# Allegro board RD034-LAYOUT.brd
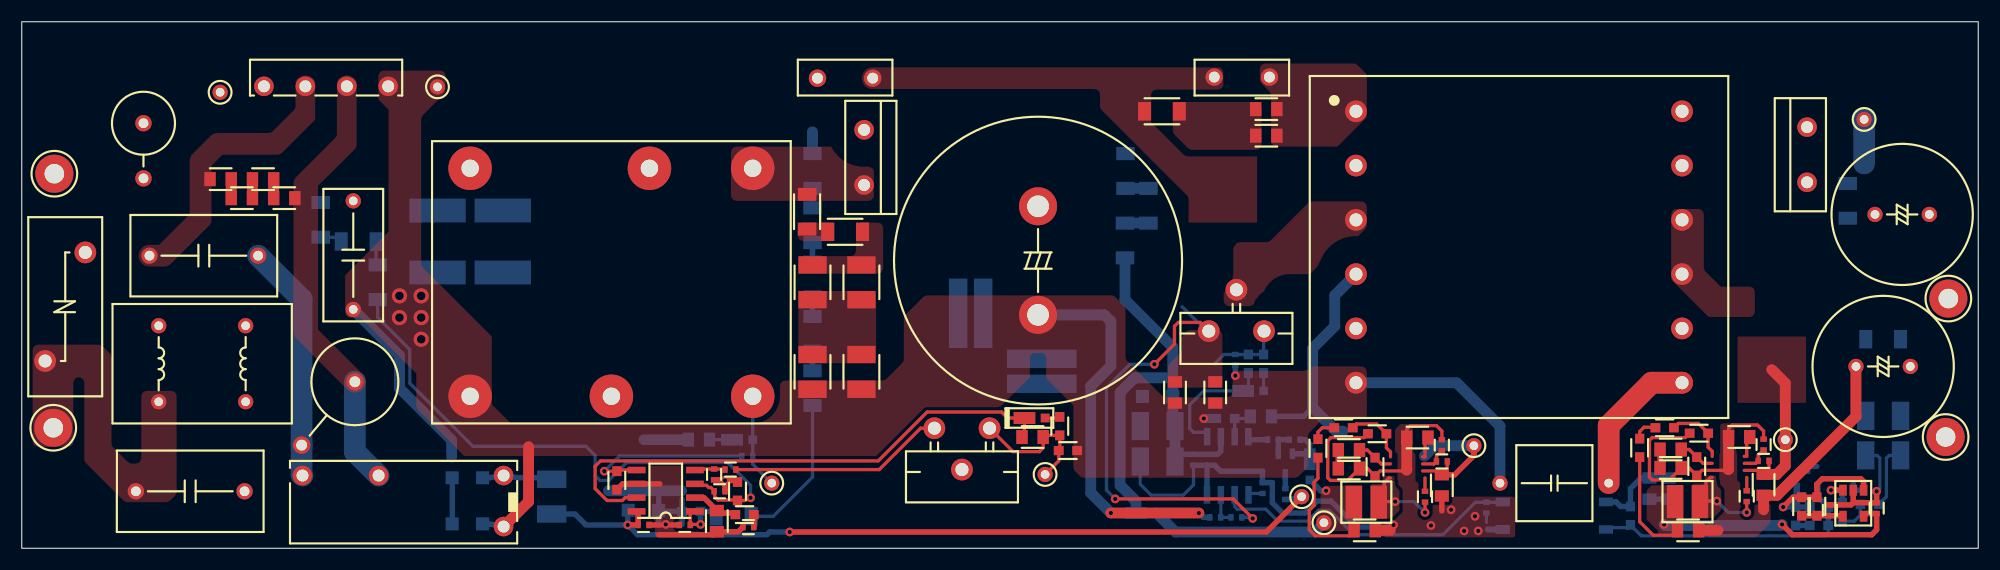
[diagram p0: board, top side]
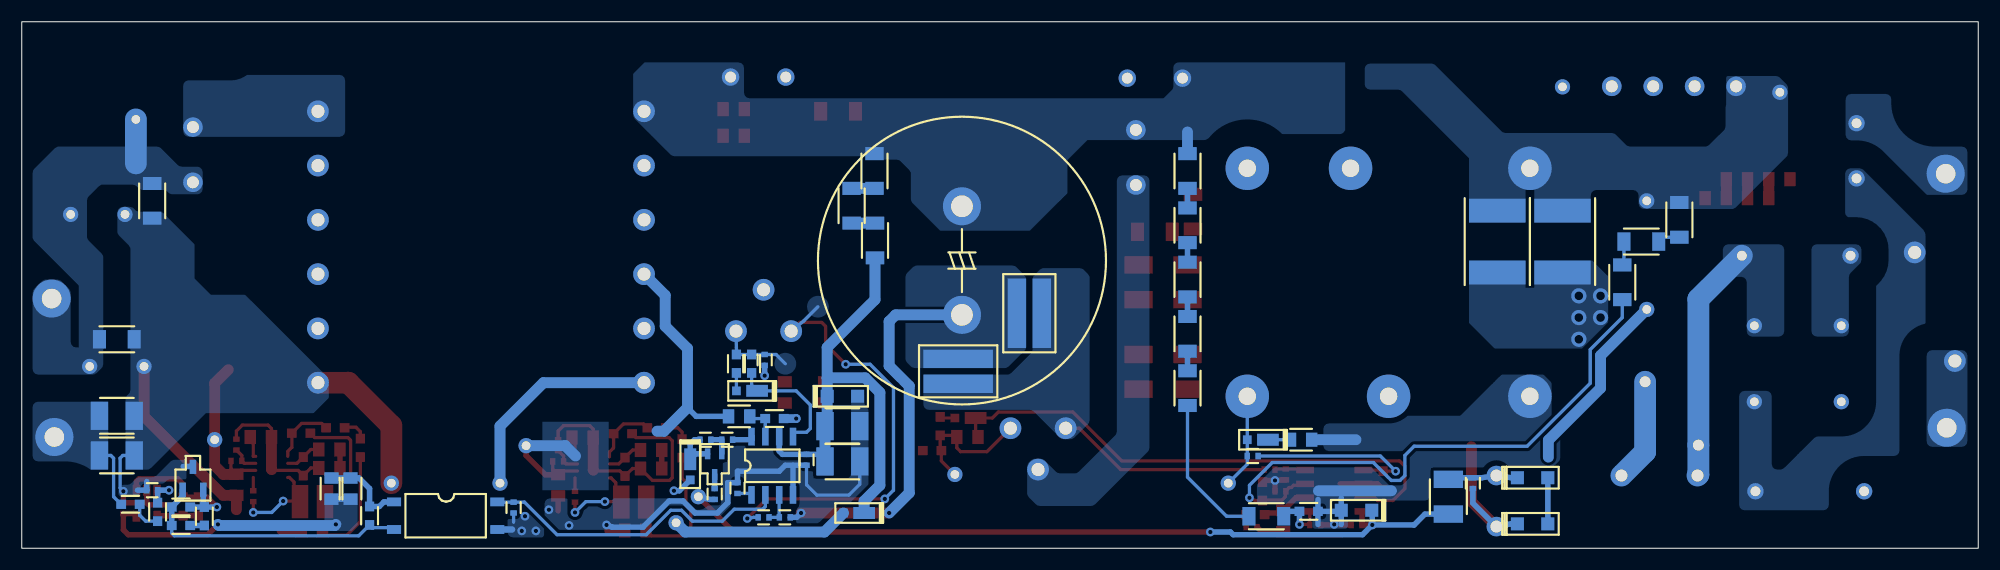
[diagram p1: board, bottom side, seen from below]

Outline 180 x 48.5 mm; copper layers: TOP, BOTTOM. Coordinates in mm from the lower left corner of the outline.
Outline path: rectangle 0,0 180,48.5

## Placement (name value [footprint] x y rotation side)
C1  -  [C1005_R_SP]  57.2 2.15 180 top
C2  -  [C1005_R_SP]  64.2 5.25 180 top
C3  -  [CA_NICHICON_D25_0_P1_1]  93.5 26.5 270 top
C4  -  [890334023025_D_SP]  15.5 5.25 0 top
C5  -  [C_12_0X5_3_P10_0_D_S_1]  30.5 27 90 top
C6  -  [C1005_R_SP]  61 2.15 0 top
C8  -  [890334023025_D_SP]  16.75 26.95 0 top
C9  -  [C1608_R_SP]  66.5 3.1 180 top
C10  -  [C1005_R_SP]  63.7 6.8 90 top
C11  -  [C2125_R_SP]  63.95 2.5 90 top
C12  -  [C1608_R_SP]  54.75 6.25 90 top
C13  -  [C1005_R_SP]  46.5 6 90 bottom
C14  -  [C3216_R_SP]  72.25 31 90 top
C15  -  [C3216_R_SP]  75.75 29.15 180 top
C100  -  [C1005_R_SP]  114.15 5.55 270 bottom
C101  -  [C1005_R_SP]  107.8 8.15 90 bottom
C102  -  [C2125_R_SP]  123.55 1.65 180 top
C103  -  [C1608_R_SP]  124.5 7.5 90 top
C104  -  [C1005_R_SP]  129.1 4.75 90 top
C105  -  [C2125_R_SP]  122.1 7.35 180 top
C106  -  [C2125_R_SP]  130.65 5.8 90 top
C107  -  [C3216_R_SP]  104.9 40.25 0 top
C108  -  [C1005_R_SP]  134.75 3.75 90 bottom
C109  -  [C_7_0X7_0_P10_0_D_SP]  141 6 180 top
C110  -  [C2125_R_SP]  160.25 5.85 90 top
C111  -  [CA_D12_5_P5_0_D_SP]  173 30.75 180 top
C112  -  [C3216_R_SP]  168 32 90 bottom
C113  -  [C1608_R_SP]  165.35 3.8 0 bottom
C114  -  [C1608_R_SP]  163.2 2.95 270 bottom
C115  -  [C1005_R_SP]  158.7 4.8 90 top
C116  -  [C2125_R_SP]  151.7 7.4 180 top
C117  -  [C1608_R_SP]  154.1 7.55 90 top
C118  -  [C2125_R_SP]  153.3 1.65 180 top
C119  -  [C1005_R_SP]  168 5.35 180 bottom
C120  -  [C1608_R_SP]  163.75 3.85 90 top
C121  -  [CA_D12_5_P5_0_D_SP]  171.25 16.75 180 top
C122  -  [C3216_R_SP]  171.25 19.25 0 bottom
C123  -  [C1005_R_SP]  170.65 3.7 270 top
C124  -  [C3225_R_SP]  104.5 8 0 bottom
C125  -  [C3225_R_SP]  104.5 11.25 0 bottom
C126  -  [C5750_R_SP]  38.25 28.25 90 bottom
C127  -  [C5750_R_SP]  44.25 28.25 90 bottom
CAM1  -  [S_LOGO_TOSHIBA]  58.95 42.23 0 top
D1  -  [TO_TO_220_2L_D_SP]  77.5 36 270 top
D3  -  [TO_3_2B1A_R_SP]  93.2 12 180 top
D4  -  [SHINDENGEN_D3K_D_SP]  28 44.9 0 top
D8  -  [TO_3_2A1A_R_SP]  57.2 3.5 180 bottom
D9  -  [TO_3_2B1A_R_SP]  66.3 10 180 bottom
D10  -  [TO_3_2A1S_R_SP]  41 2.25 0 bottom
D11  -  [TO_3_2A1S_R_SP]  41 6.5 0 bottom
D100  -  [TO_3_2A1A_R_SP]  104.5 14 0 bottom
D101  -  [TO_3_2B1A_R_SP]  113.3 14.5 180 bottom
D105  -  [TO_TO_220_2L_D_SP]  164.25 36.25 90 top
D106  -  [TO_3_2B1A_R_SP]  103.45 3.25 180 bottom
D107  -  [TO_3_2B1A_R_SP]  118.5 7.25 90 bottom
DP1  -  [TP_TH1_8_L3_5_D_SP]  3 34.5 0 top
DP5  -  [TP_TH0_8_L1_4_D_SP]  69 6 0 top
DP6  -  [TP_TH0_8_L1_4_D_SP]  94.15 6.8 0 top
DP11  -  [TP_TH1_8_L3_5_D_SP]  2.9 11.1 0 top
DP107  -  [TP_TH0_8_L1_4_D_SP]  133.6 9.45 0 top
DP108  -  [TP_TH0_8_L1_4_D_SP]  119.8 2.35 0 top
DP109  -  [TP_TH0_8_L1_4_D_SP]  117.75 4.75 0 top
DP110  -  [TP_TH0_8_L1_4_D_SP]  169.5 39.5 0 top
DP111  -  [TP_TH0_8_L1_4_D_SP]  162.25 10 0 top
DP112  -  [TP_TH1_8_L3_5_D_SP]  177.25 23 0 top
DP113  -  [TP_TH1_8_L3_5_D_SP]  177 10.25 0 top
DS100  -  [TO_11_4P1A_R_SP]  141 3 270 bottom
F1  -  [LITTEL_477_TATE1_D_S_1]  11.2 39.15 270 top
IC1  -  [TI_D8_R_SP]  59.25 5.3 90 top
IC100  -  [TI_D8_R_SP]  110.95 7.6 180 bottom
IC103  -  [ON_TSOP_5_R_SP]  168.5 4.15 180 top
IC104  -  [TI_SOT_23_3_DBZ_1_R__1]  164.25 6.45 180 bottom
L1  -  [TDK_PFC3125ER_D_SP]  54.25 24.5 90 top
L2  -  [TDK_B82730U_D_SP]  16.6 17 0 top
L100  -  [MURATA_8200_R_SP]  123.7 4.25 180 top
L101  -  [MURATA_8200_R_SP]  153.25 4.3 180 top
Q1  -  [TO_2_10U1S_GDS_D_SP]  86.5 7.25 180 top
Q100  -  [TO_2_2E1A_BEC_R_SP]  116.25 7.75 0 bottom
Q101  -  [TO_2_10U1S_GDS_D_SP#2]  111.75 20 180 top
R1  -  [R1608_R_SP]  61.6 3.4 0 bottom
R2  -  [R3216_R_SP]  72.75 29.75 90 bottom
R3  -  [R1608_R_SP]  65.85 5.25 270 top
R5  -  [R3216_R_SP]  31 28.25 180 bottom
R6  -  [R2125_R_SP]  62.3 10 0 bottom
R7  -  [PANA_ERJA1_R_SP]  87.3 21.65 90 bottom
R8  -  [R3216_R_SP]  27.5 30.25 90 bottom
R9  -  [R3216_R_SP]  72.75 24.75 90 bottom
R10  -  [R2125_R_SP]  93 10.25 0 top
R11  -  [R1005_R_SP]  65.2 7.25 0 top
R12  -  [R1608_R_SP]  95.5 11.25 270 top
R13  -  [R1005_R_SP]  66.85 1.95 0 top
R14  -  [R1005_R_SP]  66.75 8.5 180 bottom
R15  -  [R_25_0X8_0_P30_48_D__1]  25.75 9.5 230 top
R16  -  [R3226_R_SP]  48.75 4.75 270 bottom
R17  -  [R1608_R_SP]  96.25 9 0 top
R18  -  [R3216_R_SP]  65.5 2.95 0 bottom
R19  -  [R3225_R_SP]  77.25 24.5 90 top
R20  -  [R3225_R_SP]  77.25 16.25 90 top
R21  -  [R3225_R_SP]  72.75 24.5 90 top
R22  -  [R3225_R_SP]  72.75 16.25 90 top
R23  -  [R3216_R_SP]  72.75 19.75 90 bottom
R24  -  [R3216_R_SP]  72.75 14.75 90 bottom
R25  -  [R3216_R_SP]  32.75 24.5 90 bottom
R26  -  [PANA_ERJA1_R_SP]  93.85 16.3 180 bottom
R100  -  [R1005_R_SP]  116.25 5 90 bottom
R101  -  [R1005_R_SP]  117.1 10 0 bottom
R102  -  [R1005_R_SP]  115.1 10 180 bottom
R103  -  [R1608_R_SP]  121.6 11.1 180 top
R104  -  [R1608_R_SP]  124.7 10.55 0 top
R105  -  [R3216_R_SP]  101.55 34.75 270 bottom
R106  -  [R3216_R_SP]  103.65 31.55 90 bottom
R107  -  [R3216_R_SP]  101.5 28.35 270 bottom
R108  -  [R1005_R_SP]  109.8 2.85 0 bottom
R109  -  [R2125_R_SP]  122.1 9.05 0 top
R110  -  [R1005_R_SP]  111.75 2.85 0 bottom
R111  -  [R1608_R_SP]  114.25 17 90 bottom
R112  -  [R1608_R_SP]  112.85 17 90 bottom
R113  -  [R2125_R_SP]  128.4 10.2 0 top
R114  -  [R1005_R_SP]  111.65 17.35 90 bottom
R115  -  [R1005_R_SP]  130.65 8 0 top
R116  -  [R1005_R_SP]  130.65 9.5 270 top
R117  -  [R2125_R_SP]  109.8 14.35 90 top
R118  -  [R2125_R_SP]  114.5 38 0 top
R119  -  [R1608_R_SP]  110.75 11.95 0 bottom
R120  -  [NIKKOHM_TO_126_D_SP]  112.25 43.4 0 top
R121  -  [R2125_R_SP]  114 12.15 0 bottom
R122  -  [R1608_R_SP]  148 3 90 bottom
R123  -  [R1005_R_SP]  160.25 8.05 0 top
R124  -  [R1005_R_SP]  160.25 9.55 270 top
R125  -  [R2125_R_SP]  158 10.25 0 top
R126  -  [R1608_R_SP]  165.35 2.1 180 bottom
R127  -  [R2125_R_SP]  149.75 5.5 90 bottom
R128  -  [R2125_R_SP]  151.5 5.5 90 bottom
R129  -  [R2125_R_SP]  151.7 9.1 0 top
R130  -  [R1608_R_SP]  151.15 11.1 180 top
R131  -  [R1608_R_SP]  154.3 10.6 0 top
R132  -  [R1608_R_SP]  167.5 3.35 270 bottom
R133  -  [R3225_R_SP]  171.25 12.2 0 bottom
R134  -  [R3225_R_SP]  171.25 8.55 0 bottom
R135  -  [R1608_R_SP]  165.15 3.85 270 top
R136  -  [R1005_R_SP]  166.35 3.5 90 top
R137  -  [R2125_R_SP]  106.1 14.35 90 top
R138  -  [NIKKOHM_TO_126_D_SP]  75.75 43.3 180 top
R139  -  [R3216_R_SP]  72.75 34.75 90 bottom
R140  -  [R1608_R_SP]  170 4.05 0 bottom
R141  -  [R1608_R_SP]  119.25 9.2 270 top
R142  -  [R1608_R_SP]  148.85 9.25 270 top
R145  -  [R2125_R_SP]  114.5 40.45 0 top
R146  -  [R2125_R_SP]  24.15 32.25 0 top
R147  -  [R2125_R_SP]  22.2 34 0 top
R148  -  [R2125_R_SP]  20.25 32.25 0 top
R149  -  [R2125_R_SP]  18.3 34 0 top
RY1  -  [ALDP1XXW_D_SP]  35.5 4.25 180 top
T1  -  [EER28LH_D_SP]  137.75 27.75 0 top
TP3  -  [TP_TH0_8_L1_4_D_SP]  18.25 42 0 top
TP4  -  [TP_TH0_8_L1_4_D_SP]  38.25 42.5 0 top
VR1  -  [ERZE14A511_D_SP]  4 22.25 90 top

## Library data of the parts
C1 C13 C101 C108 C119 C123 = GRM155R61E104KA87D: alternate symbols: (SP_C1005_R_SP,C1005_S_R_SP)
C2 C6 C10 = GRM155R61E102KA01: alternate symbols: (SP_C1005_R_SP,C1005_S_R_SP)
C3 = LLG2W151MELA25: alternate symbols: ()
C4 C8 = 890334023025: alternate symbols: ()
C5 = ECQE6223KF: alternate symbols: ()
C9 = C1608X5R1E475K080AC: alternate symbols: (C1608_JSK_R_SP)
C11 = C0805C564K5RACTU: alternate symbols: (C2125_JSK_R_SP)
C12 = GRM1885C2A470JA01D: alternate symbols: (C1608_JSK_R_SP)
C14 C15 = C3216: alternate symbols: (C3216_JSK_R_SP)
C100 = CM05: alternate symbols: (SP_C1005_R_SP,C1005_S_R_SP)
C102 C118 = C2012X5R1E106K125AB: alternate symbols: (C2125_JSK_R_SP)
C103 C117 = GRM1885C2A5R0CA01D: alternate symbols: (C1608_JSK_R_SP)
C104 C115 = C1005X7S2A103K050BB: alternate symbols: (SP_C1005_R_SP,C1005_S_R_SP)
C105 C116 = C0805C563K1RACTU: alternate symbols: (C2125_JSK_R_SP)
C106 C110 = C2012X7S2A105K125AE: alternate symbols: (C2125_JSK_R_SP)
C107 = GRM31BR72J682KW01L: alternate symbols: (C3216_JSK_R_SP)
C109 = DE1B3KX471KA4BN01F: alternate symbols: ()
C111 C121 = EEUEE2C101: alternate symbols: ()
C112 C122 = GRM31CR72E104KW03L: alternate symbols: (C3216_JSK_R_SP)
C113 = TMK107BJ104KAHT: alternate symbols: (C1608_JSK_R_SP)
C114 = GRM188C81E105KAADD: alternate symbols: (C1608_JSK_R_SP)
C120 = C1608: alternate symbols: (C1608_JSK_R_SP)
C124 C125 = GMK325BJ106KN-T: alternate symbols: (C3225_JSK_R_SP)
C126 C127 = C5750X7T2J474K250KC: alternate symbols: (C5750_JSK_R_SP)
CAM1 = S_LOGO_TOSHIBA: alternate symbols: ()
D1 D105 = TRS8E65F: alternate symbols: ()
D3 D101 D106 D107 = CUS01: alternate symbols: ()
D4 = UD3KB80: alternate symbols: ()
D8 D100 = CRZ20: alternate symbols: ()
D9 = CUS04: alternate symbols: ()
D10 D11 = CRZ16: alternate symbols: ()
DP1 DP11 DP112 DP113 = TP-TH1.8-L3.5: alternate symbols: ()
DP5 DP6 DP107-DP111 TP3 TP4 = TP-TH0.8-L1.4: alternate symbols: (TP_TH0_8_L1_4_AEP_D__1)
DS100 = TLP383: alternate symbols: ()
F1 = 4773.15MXEP-AEP: alternate symbols: (LITTEL_477_TATE2_D_S_1)
IC1 = UCC28051D: alternate symbols: ()
IC100 = UCC28600DR: alternate symbols: ()
IC103 = NCV20071SN2T1G: alternate symbols: ()
IC104 = TL431AIDBZR: alternate symbols: ()
L1 = PFC3125ER-231K06B-00: alternate symbols: ()
L2 = B82730U3262A020: alternate symbols: ()
L100 L101 = 82154C: alternate symbols: ()
Q1 = TK290A60Y: alternate symbols: (TO_2_10U1S_GDS_YOKO__1,TO_2_10U1S_GDS_AEP_D_1,TO_2_10U1S_GDS_AEP1__1)
Q100 = 2SA1588: alternate symbols: ()
Q101 = TK290A65Y: alternate symbols: (TO_2_10U1S_GDS_YOKO__1,TO_2_10U1S_GDS_AEP_D_1,TO_2_10U1S_GDS_AEP1__1)
R1 = ERJPB3B6491V: alternate symbols: (R1608_AEP1_R_SP,R1608_JSK_R_SP)
R2 R9 R23 R24 = ERA8AEB2053V: alternate symbols: (R3216_JSK_R_SP)
R3 = RK73H1JTTD6801F: alternate symbols: (R1608_AEP1_R_SP,R1608_JSK_R_SP)
R5 R8 R25 = CRCW1206330KFKEA: alternate symbols: (R3216_JSK_R_SP)
R6 = ERJP06J102V: alternate symbols: (R2125_JSK_R_SP)
R7 R26 = ERJA1BFR68U: alternate symbols: ()
R10 = ERJP06J470V: alternate symbols: (R2125_JSK_R_SP)
R11 = RK73B1ETTP331J: alternate symbols: (R1005_S_R_SP,SP_R1005_R_SP)
R12 = RK73B1JTTD470J: alternate symbols: (R1608_AEP1_R_SP,R1608_JSK_R_SP)
R13 = ERJPA2D3301X: alternate symbols: (R1005_S_R_SP,SP_R1005_R_SP)
R14 = RK73B1ETTP333J: alternate symbols: (R1005_S_R_SP,SP_R1005_R_SP)
R15 = ROX5SG15R: alternate symbols: (R_25_0x8_0_P7_62_TAT_2,R_25_0x8_0_P7_62_TAT_1)
R16 = RK73H2ETTD2200F: alternate symbols: (R3226_JSK_R_SP)
R17 = RK73B1JTTD103J: alternate symbols: (R1608_AEP1_R_SP,R1608_JSK_R_SP)
R18 = ERA8AEB1873V: alternate symbols: (R3216_JSK_R_SP)
R19-R22 = R3225: alternate symbols: (R3225_JSK_R_SP)
R100 = RK73B1ETTP100J: alternate symbols: (R1005_S_R_SP,SP_R1005_R_SP)
R101 = RK73B1ETTP681J: alternate symbols: (R1005_S_R_SP,SP_R1005_R_SP)
R102 = ERJPA2J332X: alternate symbols: (R1005_S_R_SP,SP_R1005_R_SP)
R103 = RG1608P-204-B: alternate symbols: (R1608_AEP1_R_SP,R1608_JSK_R_SP)
R104 R131 = MCR03EZPFX1002: alternate symbols: (R1608_AEP1_R_SP,R1608_JSK_R_SP)
R105-R107 = ERJ8GEYJ564V: alternate symbols: (R3216_JSK_R_SP)
R108 = ERJ2RKF1782X: alternate symbols: (R1005_S_R_SP,SP_R1005_R_SP)
R109 R129 = ERJPB6B6203V: alternate symbols: (R2125_JSK_R_SP)
R110 = RK73H1ETTP5900F: alternate symbols: (R1005_S_R_SP,SP_R1005_R_SP)
R111 R112 = RK73B1JTTD100J: alternate symbols: (R1608_AEP1_R_SP,R1608_JSK_R_SP)
R113 R125 = ERA6AEB4643V: alternate symbols: (R2125_JSK_R_SP)
R114 = RK73B1ETTP103J: alternate symbols: (R1005_S_R_SP,SP_R1005_R_SP)
R115 = RK73H1ETTP6203F: alternate symbols: (R1005_S_R_SP,SP_R1005_R_SP)
R116 = RK73H1ETTP4302F: alternate symbols: (R1005_S_R_SP,SP_R1005_R_SP)
R117 R137 = SR732ARTTDR470F: alternate symbols: (R2125_JSK_R_SP)
R118 = ERJP6WF13R0V: alternate symbols: (R2125_JSK_R_SP)
R119 = RK73H1JRTTD4702F: alternate symbols: (R1608_AEP1_R_SP,R1608_JSK_R_SP)
R120 R138 = RNP-10SA6K2JZ03: alternate symbols: ()
R121 = ERJUP6F5603V: alternate symbols: (R2125_JSK_R_SP)
R122 = RK73B1JTTD331J: alternate symbols: (R1608_AEP1_R_SP,R1608_JSK_R_SP)
R123 = RK73H1ETTP6202F: alternate symbols: (R1005_S_R_SP,SP_R1005_R_SP)
R124 = RK73H1ETTP4301F: alternate symbols: (R1005_S_R_SP,SP_R1005_R_SP)
R126 = ERA3AEB154V: alternate symbols: (R1608_AEP1_R_SP,R1608_JSK_R_SP)
R127 R128 = ERJP06J202V: alternate symbols: (R2125_JSK_R_SP)
R130 = CPF0603B215KE1: alternate symbols: (R1608_AEP1_R_SP,R1608_JSK_R_SP)
R132 = RK73H1JTTD4700F: alternate symbols: (R1608_AEP1_R_SP,R1608_JSK_R_SP)
R133 R134 = ERJ14BQF1R0U: alternate symbols: (R3225_JSK_R_SP)
R135 = ERA3AEB124V: alternate symbols: (R1608_AEP1_R_SP,R1608_JSK_R_SP)
R136 = ERA2AEB3162X: alternate symbols: (R1005_S_R_SP,SP_R1005_R_SP)
R139 = RK73Z2BTTD: alternate symbols: (R3216_JSK_R_SP)
R140-R142 = RK73Z1JTTD: alternate symbols: (R1608_AEP1_R_SP,R1608_JSK_R_SP)
R145 = R2125: alternate symbols: (R2125_JSK_R_SP)
R146-R149 = ERJ6GEYJ474V: alternate symbols: (R2125_JSK_R_SP)
RY1 = ALDP112W: alternate symbols: ()
T1 = EER28LH: alternate symbols: ()
VR1 = ERZE14A511: alternate symbols: ()

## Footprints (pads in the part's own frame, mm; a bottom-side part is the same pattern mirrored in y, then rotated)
890334023025_D_SP
  round 1.5 hole 0.9: 1(-5,0) 2(5,0)
ALDP1XXW_D_SP
  round 1.8 hole 1.1: 1(-8.83,2.25) 2(-8.83,-2.45) 3(2.67,-2.45) 4(9.67,-2.45)
C1005_R_SP
  rect 0.5x0.6 smd: 1(-0.5,0) 2(0.5,0)
C1608_R_SP
  rect 0.9x0.85 smd: 1(-0.85,0) 2(0.85,0)
C2125_R_SP
  rect 1.05x1.3 smd: 1(-0.975,0) 2(0.975,0)
C3216_R_SP
  rect 1.2x1.7 smd: 1(-1.6,0) 2(1.6,0)
C3225_R_SP
  rect 1.6x2.6 smd: 1(-1.6,0) 2(1.6,0)
C5750_R_SP
  rect 2.2x5.2 smd: 1(-2.85,0) 2(2.85,0)
C_7_0X7_0_P10_0_D_SP
  round 1.4 hole 0.8: 1(-5,0) 2(5,0)
C_12_0X5_3_P10_0_D_S_1
  round 1.4 hole 0.8: 1(-5,0) 2(5,0)
CA_D12_5_P5_0_D_SP
  round 1.4 hole 0.8: 1(-2.5,0) 2(2.5,0)
CA_NICHICON_D25_0_P1_1
  round 3.5 hole 2: 1(-5,0) 2(5,0)
EER28LH_D_SP
  round 2 hole 1.2: 1(-15,12.5) 2(-15,7.5) 3(-15,2.5) 4(-15,-2.5) 5(-15,-7.5) 6(-15,-12.5) 7(15,-12.5) 8(15,-7.5) 9(15,-2.5) 10(15,2.5) 11(15,7.5) 12(15,12.5)
ERZE14A511_D_SP
  round 2 hole 1.2: 1(-5,1.85) 2(5,-1.85)
LITTEL_477_TATE1_D_S_1
  round 1.5 hole 0.9: 1(0,0) 2(5.08,0)
MURATA_8200_R_SP
  rect 1.52x3.05 smd: 1(-1.145,0) 2(1.145,0)
NIKKOHM_TO_126_D_SP
  round 1.6 hole 1: 1(-2.54,0) 2(2.54,0)
ON_TSOP_5_R_SP
  rect 0.7x1 smd: 1(-0.95,-1.2) 2(0,-1.2) 3(0.95,-1.2) 4(0.95,1.2) 5(-0.95,1.2)
PANA_ERJA1_R_SP
  rect 6.4x1.7 smd: 1(0,1.15) 2(0,-1.15)
R1005_R_SP
  rect 0.5x0.6 smd: 1(-0.5,0) 2(0.5,0)
R1608_R_SP
  rect 0.9x0.85 smd: 1(-0.85,0) 2(0.85,0)
R2125_R_SP
  rect 1.05x1.3 smd: 1(-0.975,0) 2(0.975,0)
R3216_R_SP
  rect 1.2x1.7 smd: 1(-1.6,0) 2(1.6,0)
R3225_R_SP
  rect 1.6x2.6 smd: 1(-1.6,0) 2(1.6,0)
R3226_R_SP
  rect 1.6x2.7 smd: 1(-1.6,0) 2(1.6,0)
R_25_0X8_0_P30_48_D__1
  round 1.6 hole 1: 1(0,0) 2(-7.62,0)
SHINDENGEN_D3K_D_SP
  round 1.8 hole 1.1: 1(-5.715,-2.35) 2(-1.905,-2.35) 3(1.905,-2.35) 4(5.715,-2.35)
TDK_B82730U_D_SP
  round 1.4 hole 0.8: 1(-4,-3.5) 2(4,-3.5) 3(4,3.5) 4(-4,3.5)
TDK_PFC3125ER_D_SP
  round 4 hole 1.6: 1(-10.5,13) 3(-10.5,0) 5(-10.5,-13) 6(10.5,-13) 7(10.5,-3.5) 8(10.5,13)
TI_D8_R_SP
  rect 0.6x1.635 smd: 1(-1.905,-2.683) 2(-0.635,-2.683) 3(0.635,-2.683) 4(1.905,-2.683) 5(1.905,2.683) 6(0.635,2.683) 7(-0.635,2.683) 8(-1.905,2.683)
TI_SOT_23_3_DBZ_1_R__1
  rect 0.6x1.3 smd: 1(-0.95,-1.05) 2(0.95,-1.05) 3(0,1.05)
TO_2_2E1A_BEC_R_SP
  rect 0.5x1 smd: B(-0.65,-0.95) C(0,0.95) E(0.65,-0.95)
TO_2_10U1S_GDS_D_SP
  round 2 hole 1.2: D(0,0) G(-2.54,-3.81) S(2.54,-3.81)
TO_2_10U1S_GDS_D_SP#2
  round 2 hole 1.2: D(0,-3.81) G(-2.54,0) S(2.54,0)
TO_3_2A1A_R_SP
  rect 1.2x1.2 smd: A(-1.4,0) K(1.4,0)
TO_3_2A1S_R_SP
  rect 1.2x1.2 smd: A(-1.4,0) K(1.4,0)
TO_3_2B1A_R_SP
  rect 0.8x0.8 smd: A(-0.95,0)
  rect 2x1.1 smd: K(0.95,0)
TO_11_4P1A_R_SP
  rect 0.8x1.3 smd: 1(-1.27,-4.75) 3(1.27,-4.75) 4(1.27,4.75) 6(-1.27,4.75)
TO_TO_220_2L_D_SP
  round 1.8 hole 1.1: A(2.54,0) K(-2.54,0)
TP_TH0_8_L1_4_D_SP
  round 1.4 hole 0.8: 1(0,0)
TP_TH1_8_L3_5_D_SP
  round 3.5 hole 1.8: 1(0,0)

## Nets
PGNDA: C3.2(TP-1) C5.1(TP-1) C13.1(TP-1) C109.2(TP-1) C126.1(TP-1) C127.1(TP-1) D4.4 D10.K L1.1 R6.1(TP-1) R7.1(TP-1) R17.2(TP-1) R20.1(TP-1) R22.1(TP-1) R26.1(TP-1) R114.1(TP-1) R117.1(TP-1) R119.1(TP-1) R137.1(TP-1) RY1.1 T1.6 TP4.1
PGNDB: C109.1(TP-1) C111.2(TP-1) C112.1(TP-1) C119.1(TP-1) C121.2(TP-1) C122.1(TP-1) C123.1(TP-1) IC103.2 IC104.3 R133.1(TP-1) R134.1(TP-1) R136.2(TP-1) T1.7
S18V: C118.2(TP-1) C123.2(TP-1) IC103.5 L101.2(TP-1) R127.1(TP-1) R128.1(TP-1) R142.2(TP-1)
$BN000001: R146.1(TP-1) R147.2(TP-1)
$BN000002: R147.1(TP-1) R148.2(TP-1)
$BN000003: R148.1(TP-1) R149.2(TP-1)
FLYBACK_DGNDA: C100.1(TP-1) C101.1(TP-1) C102.1(TP-1) C103.1(TP-1) C105.1(TP-1) C106.1(TP-1) C108.1(TP-1) C124.1(TP-1) C125.1(TP-1) D100.A DS100.4 IC100.4 R104.1(TP-1) R108.1(TP-1) R113.1(TP-1) R116.1(TP-1)
FLYBACK_DGNDB: C110.1(TP-1) C116.1(TP-1) C117.1(TP-1) C118.1(TP-1) R124.1(TP-1) R125.1(TP-1) R131.1(TP-1)
P16R8V: C102.2(TP-1) D106.A D107.A DP108.1 L100.2(TP-1) R141.2(TP-1)
PAW: C106.2(TP-1) DP107.1 R115.2(TP-1)
PFB: C108.2(TP-1) DS100.6 IC100.2
PFC_DGNDA: C1.1(TP-1) C2.1(TP-1) C6.1(TP-1) C10.1(TP-1) C11.1(TP-1) C12.1(TP-1) D8.A IC1.6 R1.1(TP-1) R3.1(TP-1) R13.1(TP-1)
PFC_IN: C5.2(TP-1) C126.2(TP-1) C127.2(TP-1) D4.1 L1.8 R8.2(TP-1) TP3.1
PFC_OUT: C3.1(TP-1) D1.K R105.1(TP-1) R118.2(TP-1) R120.2(TP-1) R138.2(TP-1) R139.2(TP-1) R145.2(TP-1) T1.1
PFC_VCC: C1.2(TP-1) D8.K DP109.1 IC1.8 R16.2(TP-1) R100.1(TP-1)
SAW: C110.2(TP-1) DP111.1 R123.2(TP-1)
SFB: C119.2(TP-1) IC103.3 R132.1(TP-1)
SIG5: C100.2(TP-1) IC100.1
SIG6: Q100.C R100.2(TP-1)
SIG13: Q100.B R101.1(TP-1) R102.1(TP-1)
SIG14: IC100.8 R102.2(TP-1)
SIG17: D101.A R111.1(TP-1)
SIG18: D101.K IC100.5 R112.1(TP-1)
SIG19: Q101.G R111.2(TP-1) R112.2(TP-1) R114.2(TP-1)
SIG21: Q101.S R110.2(TP-1) R117.2(TP-1) R137.2(TP-1)
SIG24: R106.1(TP-1) R107.1(TP-1)
SIG25: R105.2(TP-1) R106.2(TP-1)
SIG27: C107.2(TP-1) R118.1(TP-1) R145.1(TP-1)
SIG30: R121.2(TP-1) T1.4
SIG36: C111.1(TP-1) C112.2(TP-1) C121.1(TP-1) C122.2(TP-1) D105.K DP110.1 DP112.1
SIG38: D105.A T1.12
SIG39: T1.9 T1.10
SIG46: IC100.7 R119.2(TP-1) R121.1(TP-1)
SIG47: Q101.D T1.3
SIG48: DP1.1 F1.1(TP-1)
SIG50: D10.A D11.A
SIG56: C4.2(TP-1) F1.2(TP-1) L2.2 VR1.2(TP-1)
SIG57: C4.1(TP-1) DP11.1 L2.1 VR1.1(TP-1)
SIG102: C113.2(TP-1) DS100.3 IC104.1 R122.1(TP-1) R126.1(TP-1)
SIG104: DS100.1 R122.2(TP-1) R127.2(TP-1) R128.2(TP-1)
SIG108: C114.2(TP-1) R126.2(TP-1)
SIG109: C113.1(TP-1) C114.1(TP-1) C120.2(TP-1) IC103.1 IC104.2 R135.1(TP-1)
SIG114: C120.1(TP-1) IC103.4 R135.2(TP-1) R136.1(TP-1)
SIG116: C104.1(TP-1) L100.1(TP-1)
SIG118: C105.2(TP-1) R109.1(TP-1)
SIG120: R115.1(TP-1) R116.2(TP-1)
SIG121: C103.2(TP-1) R109.2(TP-1)
SIG122: R103.1(TP-1) R104.2(TP-1)
SIG124: R113.2(TP-1)
SIG125: C104.2(TP-1)
SIG126: R125.2(TP-1)
SIG128: C117.2(TP-1) R129.2(TP-1)
SIG129: R123.1(TP-1) R124.2(TP-1)
SIG131: C116.2(TP-1) R129.1(TP-1)
SIG132: C115.2(TP-1)
SIG133: R130.1(TP-1) R131.2(TP-1)
SIG135: C115.1(TP-1) L101.1(TP-1)
SIG136: R5.1(TP-1) R25.2(TP-1)
SIG137: R5.2(TP-1) R8.1(TP-1)
SIG138: C9.1(TP-1) R13.2(TP-1)
SIG141: C15.1(TP-1) R19.2(TP-1) R21.2(TP-1)
SIG142: C9.2(TP-1) C11.2(TP-1) IC1.2
SIG143: C2.2(TP-1) IC1.3 R3.2(TP-1) R25.1(TP-1)
SIG145: D3.A R12.1(TP-1)
SIG146: D3.K IC1.7 R10.1(TP-1)
SIG147: DP6.1 Q1.G R10.2(TP-1) R12.2(TP-1) R17.1(TP-1)
SIG148: C14.1(TP-1) C15.2(TP-1)
SIG149: C14.2(TP-1) D1.A L1.6 Q1.D
SIG151: Q1.S R7.2(TP-1) R11.2(TP-1) R26.2(TP-1)
SIG152: C10.2(TP-1) IC1.4 R11.1(TP-1)
SIG153: C12.2(TP-1) IC1.5 R14.2(TP-1)
SIG156: R2.1(TP-1) R9.2(TP-1)
SIG160: C6.2(TP-1) IC1.1 R1.2(TP-1) R18.1(TP-1)
SIG162: D9.K R6.2(TP-1)
SIG163: D9.A DP5.1 L1.5 R14.1(TP-1)
SIG166: R23.1(TP-1) R24.2(TP-1)
SIG167: R18.2(TP-1) R24.1(TP-1)
SIG178: C13.2(TP-1) D11.K R16.1(TP-1) RY1.2
SIG179: R19.1(TP-1) R20.2(TP-1) R21.1(TP-1) R22.2(TP-1)
SIG187: R2.2(TP-1) R139.1(TP-1)
SIG188: R132.2(TP-1) R140.1(TP-1)
SIG189: R103.2(TP-1) R141.1(TP-1)
SIG190: R130.2(TP-1) R142.1(TP-1)
SIG193: DP113.1 R133.2(TP-1) R134.2(TP-1) R140.2(TP-1)
SIG201: C107.1(TP-1) R120.1(TP-1) R138.1(TP-1)
SIG204: D4.3 R15.2(TP-1) R146.2(TP-1) RY1.3
SIG209: D107.K Q100.E R101.2(TP-1)
SIG210: C101.2(TP-1) C124.2(TP-1) C125.2(TP-1) D100.K D106.K IC100.6 R107.2(TP-1)
SIG211: IC100.3 R108.2(TP-1) R110.1(TP-1)
SIG212: R9.1(TP-1) R23.2(TP-1)
SIG213: C8.2(TP-1) L2.3 R15.1(TP-1) RY1.4
SIG214: C8.1(TP-1) D4.2 L2.4 R149.1(TP-1)

Pads without a net: L1 3 7; T1 2 5 8 11

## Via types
v1: diameter 0.8, hole 0.4, TOP to BOTTOM, 30 vias
v2: diameter 1.4, hole 0.8, TOP to BOTTOM, 5 vias

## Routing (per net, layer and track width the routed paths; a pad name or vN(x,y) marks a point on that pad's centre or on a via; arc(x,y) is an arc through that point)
PGNDA: length 58.3
  TOP w1: RY1.1 46.63,4.3 46.63,9.35
  BOTTOM w0.5: v1(111.65,15.9) R114.1 ; D10.K 43,2.25 RY1.1 46.5,4.17 C13.1
  BOTTOM w0.8: R119.1 v1(108.75,11.95)
  BOTTOM w1: C109.2 136,11.25 132,15.25 T1.6 ; C5.1 34.75,17.75 34.75,14.75 39.55,9.95 39.55,8.4 ; 57.25,10 R6.1
  vias: v2(34.75,23.25) v2(34.75,21.25) v2(36.75,23.25) v2(36.75,21.25) v2(36.75,19.25)
PGNDB: length 27.4
  TOP w0.5: R136.2 168.3,4 168.5,4.2 ; 168.5,4.2 C123.1 v1(170.65,5.25) ; 168.5,4.2 IC103.2
  TOP w2: C109.1 146,11.3 149.95,15.25 T1.7
  BOTTOM w0.3: R134.1 170.7,8.55 170.95,8.3 170.95,5.55 v1(170.65,5.25)
  BOTTOM w0.5: IC104.3 164.25,7.54 165.15,7.54 ; 169.35,5.35 IC103.2 168.5,6.15
S18V: length 35.2
  TOP w0.3: R142.2 148.85,2.45 150.1,1.2 152.32,1.2 152.32,1.65
  TOP w0.5: IC103.5 169.7,3.2 C123.2 170.65,1.7 170.2,1.25 162.9,1.25 v1(161.95,2.2)
  BOTTOM w0.5: R128.1 R127.1
  BOTTOM w1: v1(151.1,2.2) 151.2,2.1 161.85,2.1 v1(161.95,2.2)
$BN000001: length 1.8
  TOP w1: R147.2 23.18,32.25
$BN000002: length 1.8
  TOP w1: R147.1 R148.2
$BN000003: length 1.8
  TOP w1: R149.2 R148.1
FLYBACK_DGNDA: length 99.8
  TOP w0.3: 127.42,10.2 127.42,10.97 127.75,11.3 130.15,11.3 130.65,10.8 R116.1 ; 127.4,7.45 127.08,7.12 124.97,7.12 C103.1 123.8,7.35 123.08,7.35 121.97,6.25 120.4,6.25 120.15,6.5 120.15,9.9 120.45,10.2 123.5,10.2 R104.1
  TOP w0.5: C106.1 130.65,3.45
  TOP w1: C102.1 125.9,1.65 ; v1(100.2,3.25) v1(108.3,3.25) ; 127.42,9.95 127.42,7.22 127.4,7.2
  BOTTOM w0.3: C124.1 102.9,5.9 103.9,4.9 106.85,4.9 107.8,5.85 C101.1 ; C108.1 134.75,2.4
  BOTTOM w0.5: v1(126.2,2.15) 125.71,1.98 125.71,1.95 122.85,1.95 120.45,4.35 119.15,4.35 118.05,3.25 116,3.25 115.05,4.2 115.05,6.05 C100.1 114.15,7.1 110.3,7.1 109.75,7.65 109.05,7.65 ; IC100.4 109.05,7.65 ; 109.05,7.65 C101.1 ; R108.1 108.7,2.85 v1(108.3,3.25)
  BOTTOM w0.6: DS100.4 134.9,1.73
  BOTTOM w1: v1(100.2,3.25) 98.35,5.1 98.35,14.95 100.2,16.8 100.2,20.9 99.6,21.5 93.5,21.5
  vias: v1(129.65,2.1) v1(131.5,3.55) v1(132.7,1.6) v1(133.7,2.95) v1(134,1.6)
FLYBACK_DGNDB: length 42.9
  TOP w0.3: 157,7.5 156.68,7.17 154.57,7.17 C117.1 153.4,7.4 152.68,7.4 151.57,6.3 150,6.3 149.75,6.55 149.75,9.95 150,10.2 153.05,10.2 R131.1 ; R125.1 157.03,11.03 157.35,11.35 159.7,11.35 160.25,10.8 R124.1
  TOP w1: 160.25,3.55 C110.1 161.47,4.88 168.75,12.15 168.75,16.75 ; 157.03,10 157.03,7.28 157,7.25 ; C118.1 156.05,1.65
P16R8V: length 29.9
  TOP w0.3: R141.2 119.25,6.45 118.9,6.1 118.9,3.95 118.45,3.5 118.45,1.7 119,1.15 122.08,1.15 C102.2
  BOTTOM w0.5: v1(120,5.3) 119.5,5.3 D107.A
  BOTTOM w1: D106.A 106.15,1.5 118.95,1.5 DP108.1
PAW: length 12.9
  TOP w0.3: 128.88,7.12 130.3,7.12 130.65,6.78 131.15,7.28 R115.2
  TOP w0.5: DP107.1 133.6,8.55 131.82,6.78 130.65,6.78
  BOTTOM w1: DP107.1 130,9.45 129.05,8.5
PFB: length 28.9
  BOTTOM w0.3: 111.58,4.92 111.58,3.85 111.83,3.6 114.45,3.6 115.55,2.5 118.3,2.5 119.3,3.5 120.3,3.5 122.55,1.25 130.75,1.25 133.75,4.25 C108.2 136.23,4.25 DS100.6
PFC_DGNDA: length 30.9
  TOP w0.5: R13.1 65.92,1.52 C11.1 63.67,1.25 58.6,1.25 ; C2.1 v1(64.7,6.25) ; v1(64.7,6.25) 64.1,6.3 C10.1 ; v1(64.7,6.25) 65.7,6.25 R3.1 ; C12.1 55.28,5.93 IC1.6 58.7,5.93 ; C1.1 58.75,2.15 ; C6.1 59.7,2.15
  BOTTOM w0.5: D8.A 58.7,3.4 R1.1 ; D8.A 58.6,2.2 ; D8.A 58.6,4.65 ; R1.1 60.75,2.2 ; R1.1 60.75,4.5
  BOTTOM w1: 60.7,5.3 53.98,5.3
  vias: v1(59.25,2.2)
PFC_OUT: length 2
  BOTTOM w1: R139.2 72.75,38.35
PFC_VCC: length 76.5
  TOP w0.5: 56.57,3.4 56.7,3.4 C1.2 v1(55.75,2.15) ; DP109.1 114.5,1.5 v1(70.65,1.5)
  BOTTOM w0.5: v1(70.65,1.5) 68.8,1.5 68.55,1.25 56.65,1.25 v1(55.75,2.15) ; R100.1 116.73,4.5 DP109.1 ; R16.2 50.9,3.15 51.9,2.15 v1(55.75,2.15) ; D8.K 55.75,3.45 v1(55.75,2.15)
SAW: length 15.1
  TOP w0.3: R123.2 160.75,7.33 C110.2 159.9,7.17 158.47,7.17
  TOP w1: C110.2 160.28,6.8 161.45,6.8 162.25,7.6 DP111.1 162.25,15.2 161,16.45
SFB: length 3.3
  TOP w0.5: IC103.3 v1(166.45,5.35)
  BOTTOM w0.5: R132.1 C119.2 v1(166.45,5.35)
SIG5: length 1.3
  BOTTOM w0.3: IC100.1 112.99,5.05 C100.2
SIG6: length 1.3
  BOTTOM w0.5: Q100.C R100.2
SIG13: length 2.3
  BOTTOM w0.5: R101.1 R102.1 Q100.B
SIG14: length 2
  BOTTOM w0.5: R102.2 112.86,10 IC100.8
SIG17: length 1.6
  BOTTOM w0.3: R111.1 D101.A
SIG18: length 11.6
  BOTTOM w0.3: R112.1 112.85,15 D101.K 108.75,14.5 107.45,13.2 107.45,11.03 107.8,10.68 109.05,10.68 IC100.5
SIG19: length 7
  BOTTOM w0.3: Q101.G 114.25,18.5 R111.2 R112.2 R114.2 110.6,17.85 109.75,17
SIG21: length 41.5
  TOP w0.3: Q101.S 108.41,20.8 106.4,20.8 106.05,20.45 106.05,18.8 v1(104.2,16.95) ; v1(113.25,2.75) 111.45,4.55 v1(100.6,4.55)
  BOTTOM w0.3: R110.2 112.66,2.85 v1(113.25,2.75) ; 106.75,22.25 108.05,20.95 Q101.S ; v1(100.6,4.55) 99.8,5.35 99.8,14.8 101.95,16.95 v1(104.2,16.95)
SIG24: length 2.2
  BOTTOM w1: R106.1 R107.1
SIG25: length 2.1
  BOTTOM w1: R106.2 R105.2
SIG30: length 21.8
  BOTTOM w0.5: R121.2 117.95,12.15 118.75,12.95
  BOTTOM w1: 121.55,10.79 120.91,10.79 118.75,12.95 118.75,18.41 120.8,20.46 120.8,23.3 T1.4
SIG36: length 4
  BOTTOM w2: DP110.1 169.5,35.45
SIG46: length 3.2
  BOTTOM w0.3: 111.58,10.28 111.6,10.3 R119.2 112.83,11.95 R121.1
SIG50: length 4.2
  BOTTOM w0.5: D11.A D10.A
SIG102: length 25.6
  BOTTOM w0.3: DS100.3 145.92,1.9 147.75,1.9 R122.1 149,1.15 165.95,1.15 166.2,1.4 R126.1
  BOTTOM w0.5: IC104.1 165.2,4.8 C113.2 R126.1
SIG104: length 8
  BOTTOM w0.5: R128.2 R127.2 148.97,6.47 148,5.5 R122.2 147.1,3.85 146.68,4.27 DS100.1
SIG108: length 1.3
  BOTTOM w0.5: R126.2 C114.2
SIG109: length 14.2
  TOP w0.5: IC103.1 169.45,6.15 169.2,6.4 165.65,6.4 165.15,5.9 R135.1 C120.2 162.95,4.7 v1(162.05,3.8)
  BOTTOM w0.5: C114.1 163.3,3.9 IC104.2 ; C114.1 v1(162.05,3.8) ; C114.1 C113.1
SIG114: length 3.8
  TOP w0.5: IC103.4 167.5,3 R136.1 R135.2 C120.1
SIG116: length 8.3
  TOP w0.3: 125.92,6.47 125.78,6.47 125.35,6.05 125.35,4.75 124.89,4.3 ; C104.1 v1(129.1,3.3) ; L100.1 124.89,4.3 ; 124.89,4.3 v1(126.35,4.3)
  BOTTOM w0.3: v1(126.35,4.3) 128.1,4.3 v1(129.1,3.3)
SIG118: length 1.7
  TOP w0.5: R109.1 C105.2
SIG120: length 2.6
  TOP w0.3: R116.2 130.15,8.5 R115.1 129.93,7.78 128.88,7.78
SIG121: length 3.4
  TOP w0.3: 123.08,9.05 123.8,9.05 C103.2 125.08,7.78 125.92,7.78
SIG122: length 5.9
  TOP w0.3: R103.1 122.8,11.45 124.65,11.45 R104.2 125.55,9.25 125.92,8.88 125.92,8.43
SIG124: length 2.1
  TOP w0.3: 128.88,8.43 129.1,8.43 129.1,9.93 R113.2
SIG125: length 1.2
  TOP w0.3: C104.2 129.1,6.47
SIG126: length 2.1
  TOP w0.3: R125.2 158.7,9.97 158.7,8.47 158.47,8.47
SIG128: length 3.4
  TOP w0.3: 152.68,9.1 153.4,9.1 C117.2 154.68,7.83 155.53,7.83
SIG129: length 2.6
  TOP w0.3: R124.2 159.75,8.55 R123.1 159.53,7.83 158.47,7.83
SIG131: length 1.7
  TOP w0.5: R129.1 C116.2
SIG132: length 1.2
  TOP w0.3: C115.2 158.7,6.53
SIG133: length 6
  TOP w0.3: 155.53,8.47 155.53,8.93 155.15,9.3 R131.2 154.25,11.5 152.4,11.5 R130.1
SIG135: length 8.4
  TOP w0.3: v1(155.95,4.35) 154.5,4.35 ; 154.5,4.35 154.95,4.8 154.95,6.1 155.38,6.53 155.53,6.53 ; 154.5,4.35 154.44,4.3 ; C115.1 v1(158.7,3.3)
  BOTTOM w0.3: v1(155.95,4.35) 157,3.3 v1(158.7,3.3)
SIG136: length 2.2
  BOTTOM w0.3: R5.1 32.6,26.25 R25.2
SIG137: length 2.1
  BOTTOM w0.3: R8.1 29,28.65 R5.2
SIG138: length 1.2
  TOP w0.5: R13.2 C9.1
SIG142: length 4.4
  TOP w0.5: IC1.2 62.76,4.67 C11.2 64.17,3.25 65.5,3.25 C9.2
SIG143: length 53.9
  TOP w0.3: IC1.3 62.07,5.8 63,5.8 63.2,5.6 63.4,5.6 63.75,5.25 ; v1(67.05,4.65) 66.5,4.4 R3.2 65.8,4.45 64.05,4.45 63.75,4.75 63.75,5.25 ; 63.75,5.25 C2.2
  BOTTOM w0.3: R25.1 32.75,21.25 35.7,18.3 35.7,15.2 41.5,9.4 51.9,9.4 52.75,8.55 52.75,6.7 53.2,6.25 54,6.25 55.65,7.9 64.95,7.9 67.05,5.8 v1(67.05,4.65)
SIG145: length 1.4
  TOP w0.3: D3.A 95.4,12 R12.1
SIG146: length 50.1
  TOP w0.3: IC1.7 55.52,4.67 55.25,4.4 53.85,4.4 52.75,5.5 52.75,7.55 53.25,8.05 78.8,8.05 83.3,12.55 90.15,12.55 90.7,12 D3.K 92.25,10.47 R10.1
SIG147: length 12.7
  TOP w0.3: DP6.1 95.4,8.05 R17.1 95.5,9.1 R12.2 94.12,10.4 R10.2 93.97,9.25 93.62,8.9 91.2,8.9 Q1.G
SIG151: length 19.8
  TOP w0.3: Q1.S 82.7,11.06 78.89,7.25 R11.2
SIG152: length 2.8
  TOP w0.3: R11.1 64.65,7.3 C10.2 62.03,7.3 IC1.4
SIG153: length 16.2
  TOP w0.3: IC1.5 54.85,7.21 C12.2 v1(53.6,7.1)
  BOTTOM w0.3: v1(53.6,7.1) 55,8.5 R14.2
SIG156: length 1.8
  BOTTOM w0.5: R2.1 R9.2
SIG160: length 5.5
  TOP w0.3: 61.93,3.4 61.5,3.4 C6.2 61.55,2.2 v1(62.45,2.2)
  BOTTOM w0.5: v1(62.45,2.2) R1.2 63.45,3.4 R18.1
SIG162: length 2.1
  BOTTOM w0.3: D9.K R6.2
SIG163: length 8.7
  BOTTOM w0.3: L1.5 D9.A R14.1 67.25,7.75 DP5.1
SIG166: length 1.8
  BOTTOM w0.5: R23.1 R24.2
SIG167: length 13.7
  BOTTOM w0.3: R24.1 72.75,6.55 69.15,2.95 R18.2
SIG178: length 6.4
  BOTTOM w0.5: D11.K 42.99,6.5 RY1.2 45.67,6.5 C13.2 48.6,6.5 R16.1
SIG187: length 1.8
  BOTTOM w0.5: R139.1 R2.2
SIG188: length 2.9
  BOTTOM w0.3: R140.1 169.15,3.05 168.6,2.5 R132.2
SIG189: length 2.3
  TOP w0.3: R103.2 119.65,11.1 119.25,10.7 R141.1
SIG190: length 2.4
  TOP w0.3: 150.35,11.15 150.3,11.15 ; 150.3,11.15 R130.2 ; 150.3,11.15 149.25,11.15 148.85,10.75 R142.1
SIG193: length 5.9
  BOTTOM w0.3: R134.2 171.8,8.55 171.55,8.3 171.55,4.75 R140.2
SIG204: length 9.5
  BOTTOM w2: R15.2 30.65,8.88 RY1.3
SIG209: length 4.3
  BOTTOM w0.5: R101.2 118.1,10 118.5,9.6 D107.K 118,8.7 Q100.E
SIG210: length 43.7
  BOTTOM w0.5: C124.2 106.75,8.65 C101.2 110.02,8.65 110.31,8.95 IC100.6
  BOTTOM w1: 105.9,15.7 102.4,15.7 101.05,14.35 101.05,5.8 102.5,4.35 D106.K ; 105.9,15.7 D100.K 105.9,11.45 C125.2 C124.2 ; 105.9,15.7 105.9,18.5 101.5,22.9 R107.2
SIG211: length 3
  BOTTOM w0.3: IC100.3 110.31,2.85 ; 110.31,2.85 R110.1 ; 110.31,2.85 R108.2
SIG212: length 1.8
  BOTTOM w0.5: R9.1 R23.2
SIG213: length 21.9
  BOTTOM w2: C8.2 25.75,22.95 R15.1 25.75,6.78 RY1.4

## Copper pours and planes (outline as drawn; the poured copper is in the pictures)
PGNDA on TOP: outline of 150 points within 29.75,6.5 123.75,44
PGNDA on BOTTOM: 89.56,16.6 89.43,16.62 89.2,16.75 87.75,18.2 87.64,18.37 87.6,18.56 87.6,24.79 87.62,24.92 87.75,25.15 88.5,25.9 88.61,25.98 88.86,26.05 97.64,26.05 97.77,26.03 98,25.9 98.55,25.35 98.63,25.24 98.7,24.99 98.7,17.46 98.68,17.33 98.55,17.1 98.2,16.75 98.09,16.67 97.84,16.6
PGNDA on BOTTOM: 53.11,8.95 53.06,8.95 53.01,8.96 52.97,8.97 52.94,9 52.22,9.72 52.07,9.82 51.9,9.85 41.75,9.85 41.69,9.86 41.64,9.89 39.29,12.24 39.26,12.29 39.25,12.35 39.25,15.15 39.26,15.21 39.32,15.32 39.93,15.93 39.98,15.97 40.1,16 43.75,16 43.81,15.99 43.92,15.93 47.58,12.27 47.69,12.21 47.75,12.2 52.46,12.2 52.51,12.19 53.34,11.67 54.25,11.5 59.75,11.5 60,11.43 60.18,11.25 60.25,11 60.25,9.45 60.18,9.2 60,9.02 59.75,8.95
PGNDB on BOTTOM: 169.55,4.78 169.3,4.84 169.12,5.03 169.05,5.28 169.05,5.6 168.95,5.85 168.7,5.95 167.16,5.95 167,5.97 166.86,6.05 166.84,6.06 166.7,6.2 166.48,6.33 166.35,6.35 165,6.35 164.89,6.39 164.85,6.5 164.85,8 164.89,8.11 165,8.15 165.94,8.15 166.07,8.13 166.3,8 167.6,6.7 167.83,6.57 167.96,6.55 169.14,6.55 169.27,6.53 169.5,6.4 169.9,6 170.13,5.87 170.26,5.85 170.6,5.85 170.85,5.78 171.03,5.6 171.1,5.35 171.1,5 171.09,4.94 171.06,4.89 170.98,4.82 170.93,4.79 170.88,4.78
PGNDB on BOTTOM: 168.46,7.25 168.33,7.27 168.1,7.4 163.05,12.45 153.21,12.45 153.15,12.46 153.11,12.49 151.79,13.81 151.76,13.85 151.75,13.91 151.75,15.44 151.77,15.57 151.9,15.8 155.1,19 159.41,23.31 159.45,23.34 159.51,23.35 162.6,23.35 164.1,24.85 164.1,27.94 164.11,28 164.14,28.04 166.95,30.85 167.06,30.93 167.31,31 169.19,31 169.44,31.07 169.55,31.15 169.7,31.3 169.81,31.38 170.06,31.45 170.7,31.45 170.95,31.38 171.13,31.2 171.2,30.95 171.2,29.16 171.18,29.03 171.05,28.8 170.15,27.9 170.02,27.67 170,27.54 170,14.59 170.07,14.34 170.15,14.23 170.36,14.02 170.39,13.98 170.43,13.87 170.45,13.74 170.45,7.75 170.38,7.5 170.2,7.32 169.95,7.25
S18V on TOP: 150.7,1.05 150.59,1.09 150.55,1.2 150.55,1.6 149.54,2.61 149.51,2.65 149.5,2.71 149.5,5.29 149.51,5.35 149.54,5.39 149.9,5.75 149.95,5.79 150.01,5.8 152.65,5.8 152.78,5.76 152.87,5.67 152.9,5.55 152.9,2.75 152.89,2.69 152.83,2.57 152.77,2.52 152.71,2.41 152.7,2.34 152.7,1.3 152.65,1.14 152.52,1.06 152.48,1.05
S18V on BOTTOM: 149.7,1.6 149.64,1.61 149.59,1.64 149.14,2.09 149.11,2.14 149.1,2.2 149.1,4.25 149.17,4.5 149.35,4.68 149.6,4.75 151.65,4.75 151.9,4.68 152.08,4.5 152.15,4.25 152.15,2.1 152.01,1.75 151.66,1.6 151.66,1.6
FLYBACK_DGNDA on TOP: outline of 88 points within 125.35,1 137.4,11.45
FLYBACK_DGNDA on BOTTOM: 132.19,1 132.07,1.03 131.98,1.12 131.94,1.25 131.94,1.74 131.95,1.8 131.99,1.85 133.34,3.2 133.44,3.28 133.69,3.35 134,3.35 134.11,3.31 134.15,3.2 134.15,3.05 134.25,2.8 134.5,2.7 135.15,2.7 135.26,2.66 135.3,2.55 135.3,1.5 135.23,1.25 135.05,1.07 134.8,1
FLYBACK_DGNDA on BOTTOM: outline of 163 points within 102.1,1.7 131.9,14.6
FLYBACK_DGNDB on TOP: 155.26,1 155.17,1.03 155.12,1.11 155.11,1.18 155.1,1.25 155.1,2.35 155.13,2.44 155.21,2.49 155.26,2.5 155.56,2.5 155.74,2.53 155.88,2.63 156.52,3.27 156.62,3.41 156.65,3.59 156.65,5.31 156.62,5.48 156.52,5.63 156.29,5.86 156.26,5.9 156.25,5.96 156.25,6.09 156.24,6.17 156.21,6.27 156.21,6.3 156.18,6.3 156.18,8.7 156.25,8.7 156.25,11.25 156.28,11.38 156.37,11.47 156.5,11.5 157.6,11.5 157.69,11.48 157.76,11.44 157.81,11.3 157.72,11.19 157.6,11.09 157.55,10.95 157.55,9.35 157.58,9.23 157.62,9.18 157.68,9.12 157.72,9.07 157.75,8.95 157.75,8.7 157.82,8.7 157.82,6.3 157.81,6.3 157.9,6.18 158.02,6.1 158.08,6.04 158.1,5.96 158.1,4.1 158.11,4.01 158.15,3.93 158.17,3.86 158.15,3.79 158.06,3.59 158.55,2.62 159.4,3.3 159.4,3.8 159.43,3.92 159.53,4.02 159.65,4.05 160.75,4.05 160.86,4.01 160.9,3.9 160.9,2.56 160.88,2.43 160.75,2.2 159.7,1.15 159.59,1.07 159.34,1
P16R8V on TOP: 122.15,1 122.04,1.04 122,1.15 122,1.6 119.56,1.6 119.5,1.61 119.46,1.64 119.14,1.96 119.11,2 119.1,2.06 119.1,3.34 119.11,3.4 119.14,3.44 119.5,3.8 119.5,5.29 119.51,5.35 119.54,5.39 119.86,5.71 119.9,5.74 119.96,5.75 123.05,5.75 123.17,5.72 123.27,5.62 123.3,5.5 123.3,2.7 123.29,2.64 123.23,2.53 123.17,2.47 123.11,2.36 123.1,2.3 123.1,1.25 123.07,1.12 122.97,1.03 122.85,1
PAW on BOTTOM: 126,5.35 126,11.65 132.1,11.65 132.1,5.35
PFC_DGNDA on TOP: 58.5,1 58.38,1.03 58.28,1.12 58.25,1.25 58.25,2.4 58.15,2.65 57.9,2.75 57.84,2.75 57.73,2.79 57.69,2.9 57.69,7.35 57.72,7.47 57.81,7.57 57.94,7.6 60.56,7.6 60.69,7.57 60.78,7.47 60.81,7.35 60.81,3 60.78,2.88 60.69,2.78 60.56,2.75 60.3,2.75 60.05,2.65 59.95,2.4 59.95,1.9 60.05,1.65 60.3,1.55 62.16,1.55 62.19,1.55 62.27,1.52 62.33,1.51 62.42,1.46 62.45,1.36 62.45,1.25 62.42,1.12 62.33,1.03 62.2,1
PFC_DGNDA on BOTTOM: outline of 89 points within 38.45,1.8 66.37,11.1
PFC_IN on BOTTOM: 36.15,30 35.9,30.07 35.72,30.25 35.65,30.5 35.65,32.5 35.58,32.75 35.4,32.93 35.15,33 31.75,33 31.5,32.93 31.32,32.75 31.25,32.5 31.25,31.75 31.18,31.5 31,31.32 30.75,31.25 22.66,31.25 22.53,31.27 22.3,31.4 17.65,36.05 17.57,36.16 17.5,36.41 17.5,42.39 17.52,42.52 17.65,42.75 18.25,43.35 18.36,43.43 18.61,43.5 23,43.5 23.05,43.49 23.1,43.48 23.17,43.42 23.19,43.34 23.19,41 23.2,40.84 23.25,40.63 23.25,38.86 23.32,38.61 23.4,38.5 24.75,37.15 24.98,37.02 25.11,37 32.04,37 32.29,37.07 32.4,37.15 33.35,38.1 33.46,38.18 33.71,38.25 43.49,38.25 43.74,38.32 43.85,38.4 49.95,44.5 50.06,44.58 50.31,44.65 55.95,44.65 56.2,44.58 56.38,44.4 56.45,44.15 56.45,42.75 56.38,42.5 56.2,42.32 55.95,42.25 53.38,42.25 53.13,42.18 53.03,42.1 46.85,35.92 46.85,30.5 46.78,30.25 46.6,30.07 46.35,30 42.15,30 41.9,30.07 41.72,30.25 41.65,30.5 41.65,33 40.85,33 40.85,30.5 40.78,30.25 40.6,30.07 40.35,30
PFC_OUT on TOP: 115.45,37 115.2,37.07 115.02,37.25 114.95,37.5 114.95,41.69 114.88,41.94 114.8,42.05 114.05,42.8 113.97,42.91 113.9,43.16 113.9,44.15 113.97,44.4 114.15,44.58 114.4,44.65 122.54,44.65 122.67,44.63 122.9,44.5 123.6,43.8 123.68,43.69 123.75,43.44 123.75,39.76 123.74,39.7 123.71,39.66 121.09,37.04 121.05,37.01 120.99,37
PFC_OUT on BOTTOM: 87.31,29.25 87.25,29.26 87.21,29.29 83.84,32.66 83.81,32.7 83.8,32.76 83.8,35.75 81.95,37.6 71.19,37.6 71.06,37.62 70.84,37.75 70.72,37.86 70.71,37.87 67.47,39.49 64.08,38.19 64.03,38.16 63.97,38.15 58.75,38.15 58.48,38.23 58.29,38.45 58.25,38.45 58.25,44.75 73.55,44.75 73.9,44.6 74.05,44.25 74.05,42.56 74.09,42.37 74.2,42.2 74.95,41.45 113.05,41.45 113.3,41.52 113.48,41.7 113.55,41.95 113.55,44.25 113.62,44.5 113.8,44.68 114.05,44.75 122.64,44.75 122.7,44.74 122.74,44.71 123.71,43.74 123.74,43.7 123.75,43.64 123.75,39.91 123.73,39.78 123.6,39.55 120.3,36.25 120.2,36.18 119.95,36.11 102.4,36.11 102.4,35.95 102.36,35.84 102.25,35.8 99.51,35.8 99.26,35.73 99.15,35.65 98.35,34.85 98.22,34.62 98.2,34.49 98.2,32.16 98.18,32.03 98.05,31.8 95.54,29.29 95.5,29.26 95.44,29.25
SAW on TOP: 157.85,13.4 157.85,19.5 164.15,19.5 164.15,13.4
SIG19 on BOTTOM: 108.75,17 110.75,17
SIG21 on TOP: 105.95,14.8 105.7,14.87 105.52,15.05 105.45,15.3 105.45,16.64 105.47,16.77 105.6,17 106.55,17.95 106.68,18.18 106.7,18.31 106.7,19.29 106.72,19.42 106.85,19.65 107.15,19.95 107.26,20.03 107.51,20.1 109.95,20.1 110.2,20.03 110.38,19.85 110.45,19.6 110.45,15.3 110.38,15.05 110.2,14.87 109.95,14.8
SIG21 on BOTTOM: 105.75,22.25 107.75,22.25
SIG27 on TOP: 107.66,36.7 107.53,36.72 107.3,36.85 106.05,38.1 105.97,38.21 105.9,38.46 105.9,40.95 105.94,41.06 106.05,41.1 113.55,41.1 113.8,41.03 113.98,40.85 114.05,40.6 114.05,37.2 113.98,36.95 113.8,36.77 113.55,36.7
SIG36 on BOTTOM: 173.46,16 173.33,16.02 173.1,16.15 172.65,16.6 172.57,16.71 172.5,16.96 172.5,26.79 172.52,26.92 172.65,27.15 173.85,28.35 173.98,28.58 174,28.71 174,32.04 173.93,32.29 173.85,32.4 172.9,33.35 172.67,33.48 172.54,33.5 169.81,33.5 169.56,33.43 169.45,33.35 169.25,33.15 169.14,33.07 168.89,33 166.96,33 166.71,32.93 166.6,32.85 166.5,32.75 166.39,32.67 166.14,32.6 163.85,32.6 163.6,32.67 163.42,32.85 163.35,33.1 163.35,34.65 163.42,34.9 163.6,35.08 163.85,35.15 165.29,35.15 165.54,35.22 165.65,35.3 167.2,36.85 167.31,36.93 167.56,37 176.59,37 176.72,36.98 176.95,36.85 178.85,34.95 178.93,34.84 179,34.59 179,28.66 178.98,28.53 178.85,28.3 174.75,24.2 174.75,18.5 175,18.5 175.25,18.57 175.43,18.75 175.5,19 175.5,23.54 175.52,23.67 175.65,23.9 176.35,24.6 176.46,24.68 176.71,24.75 177.79,24.75 177.92,24.73 178.15,24.6 178.85,23.9 178.93,23.79 179,23.54 179,16.5 178.93,16.25 178.75,16.07 178.5,16
SIG38 on BOTTOM: 150.75,37.9 150.5,37.97 150.32,38.15 150.25,38.4 150.25,43.1 150.32,43.35 150.5,43.53 150.75,43.6 159.23,43.6 159.27,43.59 160.01,43.22 160.78,43.1 164.65,43.1 164.9,43.03 165.08,42.85 165.15,42.6 165.15,38.4 165.08,38.15 164.9,37.97 164.65,37.9
SIG39 on TOP: 155.26,21.3 155.2,21.31 155.16,21.34 151.79,24.71 151.76,24.75 151.75,24.81 151.75,30.75 151.82,31 152,31.18 152.25,31.25 154.25,31.25 154.5,31.18 154.68,31 154.75,30.75 154.75,25.86 154.82,25.61 154.9,25.5 156.3,24.1 158.95,24.1 159.2,24.03 159.38,23.85 159.45,23.6 159.45,21.8 159.38,21.55 159.2,21.37 158.95,21.3
SIG47 on TOP: 111.08,22.3 110.83,22.37 110.65,22.55 110.58,22.8 110.58,23.45 110.59,23.51 111.25,24.42 111.46,25.45 111.46,27.56 111.48,27.69 111.61,27.91 111.75,28.05 111.86,28.13 112.11,28.2 114.54,28.2 114.79,28.27 114.9,28.35 118.35,31.8 118.46,31.88 118.71,31.95 123.25,31.95 123.5,31.88 123.68,31.7 123.75,31.45 123.75,29.76 123.73,29.63 123.6,29.4 122.99,28.79 122.94,28.76 122.88,28.75 120.94,28.25 119.6,26.77 119.22,25.97 119.2,25.95 119.19,25.93 118.55,25.29 118.5,25.26 118.45,25.25 116.65,25.25 115.24,24.83 114.3,23.7 114.28,23.66 114.25,23.64 113.81,23.26 113.45,22.8 113.38,22.55 113.2,22.37 112.95,22.3
SIG48 on BOTTOM: 1.5,32.55 1.25,32.62 1.07,32.8 1,33.05 1,36.5 1.07,36.75 1.25,36.93 1.5,37 4,37 6.83,38.17 8,41 8,41.35 8.07,41.6 8.25,41.78 8.5,41.85 11.7,41.85 11.95,41.78 12.13,41.6 12.2,41.35 12.2,38.07 12.13,37.82 11.95,37.64 11.7,37.57 11.2,37.57 9.86,37.3 8.73,36.54 4.77,32.59 4.73,32.56 4.67,32.55
SIG56 on BOTTOM: 14.25,3.5 14,3.57 13.82,3.75 13.75,4 13.75,5.25 12.8,7.55 10.5,8.5 7.75,8.5 7.5,8.57 7.32,8.75 7.25,9 7.25,17.75 6.61,19.6 4.88,20.72 4.85,20.81 4.85,28.72 4.93,29.1 5.14,29.43 10.57,34.85 10.67,34.93 10.92,35 11.75,35 12,34.93 12.18,34.75 12.25,34.5 12.25,30.95 12.19,30.7 12.01,30.52 11.97,30.51 11.93,30.5 11.25,30.5 10.73,30.45 10.22,30.32 9.75,30.1 9.32,29.8 8.95,29.43 8.65,29 8.43,28.53 8.3,28.02 8.25,27.5 8.25,26.56 8.3,26.04 8.43,25.53 8.65,25.06 8.95,24.63 9.13,24.44 9.36,24.21 9.39,24.16 9.4,24.1 9.4,20.75 9.4,20.74 9.4,13.56 10.34,11.24 12.65,10.3 14.74,10.3 14.87,10.28 15.1,10.15 17.85,7.4 18.08,7.27 18.21,7.25 18.5,7.25 18.75,7.32 18.93,7.5 19,7.75 19,14 19.07,14.25 19.25,14.43 19.5,14.5 21.5,14.5 21.75,14.43 21.93,14.25 22,14 22,4 21.93,3.75 21.75,3.57 21.5,3.5
SIG57 on TOP: 9.71,4.25 9.58,4.27 9.35,4.4 5.9,7.85 5.79,8.02 5.75,8.21 5.75,15.25 5.68,15.5 5.5,15.68 5.25,15.75 5,15.68 4.82,15.5 4.75,15.25 4.75,9.85 4.68,9.6 4.5,9.42 4.25,9.35 1.5,9.35 1.25,9.42 1.07,9.6 1,9.85 1,18.25 1.07,18.5 1.25,18.68 1.5,18.75 7.09,18.75 7.22,18.73 7.45,18.6 8.1,17.95 8.18,17.84 8.25,17.59 8.25,9.66 8.32,9.41 8.4,9.3 9.75,7.95 9.98,7.82 10.11,7.8 10.5,7.8 10.75,7.87 10.93,8.05 11,8.3 11,14 11.07,14.25 11.25,14.43 11.5,14.5 13.75,14.5 14,14.43 14.18,14.25 14.25,14 14.25,5.21 14.23,5.08 14.1,4.85 13.65,4.4 13.54,4.32 13.29,4.25
SIG57 on BOTTOM: 1.5,9.35 1.25,9.42 1.07,9.6 1,9.85 1,17.75 1.07,18 1.25,18.18 1.5,18.25 4.25,18.25 4.5,18.18 4.68,18 4.75,17.75 4.75,9.85 4.68,9.6 4.5,9.42 4.25,9.35
SIG116 on TOP: 124.25,2.75 124.14,2.79 124.1,2.9 124.1,5.75 124.14,5.86 124.25,5.9 124.88,5.9 124.93,5.9 124.99,5.92 125.16,6.05 125.22,6.25 125.22,6.5 125.27,6.61 125.38,6.65 126.12,6.65 126.23,6.61 126.28,6.5 126.28,6.3 126.29,6.2 126.34,6.08 126.35,6.04 126.35,5.91 126.38,5.74 126.48,5.59 126.71,5.37 126.74,5.32 126.75,5.26 126.75,3.54 126.74,3.48 126.71,3.43 126.16,2.88 126.12,2.85 126.08,2.84 125.97,2.81 125.87,2.77 125.84,2.75 125.8,2.75
SIG135 on TOP: 153.85,2.8 153.74,2.84 153.7,2.95 153.7,5.8 153.74,5.91 153.85,5.95 154.47,5.95 154.53,5.95 154.59,5.97 154.76,6.1 154.82,6.3 154.82,6.55 154.87,6.66 154.97,6.7 155.72,6.7 155.83,6.66 155.88,6.55 155.88,6.35 155.89,6.25 155.94,6.13 155.95,6.09 155.95,5.96 155.98,5.79 156.08,5.64 156.31,5.42 156.34,5.37 156.35,5.31 156.35,3.59 156.34,3.53 156.31,3.48 155.67,2.84 155.62,2.81 155.56,2.8
SIG141 on TOP: 71.95,25.3 71.7,25.37 71.52,25.55 71.45,25.8 71.45,26.4 71.52,26.65 71.7,26.83 71.95,26.9 76.25,26.9 76.5,26.97 76.68,27.15 76.75,27.4 76.75,29.5 76.82,29.75 77,29.93 77.25,30 78.75,30 79,29.93 79.18,29.75 79.25,29.5 79.25,25.8 79.18,25.55 79,25.37 78.75,25.3
SIG148 on TOP: 71.9,28.3 71.65,28.37 71.47,28.55 71.4,28.8 71.4,29.5 71.47,29.75 71.65,29.93 71.9,30 74.25,30 74.5,29.93 74.68,29.75 74.75,29.5 74.75,28.8 74.68,28.55 74.5,28.37 74.25,28.3
SIG149 on TOP: 65.75,32 65.5,32.07 65.32,32.25 65.25,32.5 65.25,36.5 65.32,36.75 65.5,36.93 65.75,37 74.38,37 74.45,36.98 75.76,35.62 77.5,35.14 77.9,35.14 78.15,35.07 78.33,34.89 78.4,34.64 78.4,32.5 78.33,32.25 78.15,32.07 77.9,32
SIG149 on BOTTOM: 81.61,3.9 81.48,3.92 81.25,4.05 76.4,8.9 76.32,9.01 76.25,9.26 76.25,33.85 76.32,34.1 76.5,34.28 76.75,34.35 78.75,34.35 79,34.28 79.18,34.1 79.25,33.85 79.25,10.76 79.32,10.51 79.4,10.4 82.75,7.05 82.98,6.92 83.11,6.9 84.49,6.9 84.74,6.97 84.85,7.05 85.9,8.1 86.01,8.18 86.26,8.25 86.79,8.25 86.92,8.23 87.15,8.1 87.35,7.9 87.43,7.79 87.5,7.54 87.5,5.06 87.48,4.93 87.35,4.7 86.7,4.05 86.59,3.97 86.34,3.9
SIG151 on BOTTOM: 83.51,10.05 83.38,10.07 83.15,10.2 81.9,11.45 81.82,11.56 81.75,11.81 81.75,24.89 81.77,25.02 81.9,25.25 82.3,25.65 82.41,25.73 82.66,25.8 85.99,25.8 86.12,25.78 86.35,25.65 86.85,25.15 86.93,25.04 87,24.79 87,18.31 87.07,18.06 87.15,17.95 88.95,16.15 89.18,16.02 89.31,16 96.55,16 96.8,15.93 96.98,15.75 97.05,15.5 97.05,13.25 96.98,13 96.8,12.82 96.55,12.75 87.26,12.75 87.01,12.68 86.9,12.6 84.5,10.2 84.39,10.12 84.14,10.05
SIG179 on TOP: 71.95,17.05 71.7,17.12 71.52,17.3 71.45,17.55 71.45,23.2 71.52,23.45 71.7,23.63 71.95,23.7 78.1,23.7 78.35,23.63 78.53,23.45 78.6,23.2 78.6,17.55 78.53,17.3 78.35,17.12 78.1,17.05
SIG193 on BOTTOM: 172.55,7.25 172.3,7.32 172.12,7.5 172.05,7.75 172.05,13 172.12,13.25 172.3,13.43 172.55,13.5 178.5,13.5 178.75,13.43 178.93,13.25 179,13 179,8.5 178.93,8.25 178.75,8.07 178.5,8 176,8 175.49,7.97 174.98,7.87 174.32,7.63 173.71,7.28 173.67,7.26 173.62,7.25
SIG201 on TOP: 107.35,30 107.35,32.15 107.31,32.34 107.2,32.5 99.35,40.35 99.27,40.46 99.2,40.71 99.2,41.8 99.13,42.05 98.95,42.23 98.7,42.3 78.29,42.3 77.29,43.3 78.29,44.3 110.05,44.3 110.3,44.23 110.48,44.05 110.55,43.8 110.55,42.75 110.48,42.5 110.3,42.32 110.05,42.25 104.4,42.25 104.15,42.18 103.97,42 103.9,41.75 103.9,39.25 106.9,36.25 107.13,36.12 107.26,36.1 113.15,36.1 113.17,36.1 113.65,36.1 113.65,30
SIG204 on TOP: 31.36,16.04 31.36,14.63 29.94,14.63 25.29,19.28 25.14,19.47 25.04,19.7 25.01,19.8 25,19.9 25,33.54 25.08,33.92 25.29,34.24 28.85,37.8 28.98,38.03 29,38.16 29,42.94 29,42.98 29.02,43.01 29.91,43.55 30.79,43.01 30.81,42.98 30.81,42.94 30.81,37.14 30.79,37.01 30.66,36.79 27.25,33.37 27.25,20.15 31.36,16.04
SIG213 on BOTTOM: 18.35,19.5 18.1,19.57 17.92,19.75 17.85,20 17.85,27.5 17.92,27.75 18.1,27.93 18.35,28 23,28 23.25,27.93 23.43,27.75 23.5,27.5 23.5,25.5 23.43,25.25 23.25,25.07 23,25 21.8,25 21.55,24.93 21.37,24.75 21.3,24.5 21.3,20 21.23,19.75 21.05,19.57 20.8,19.5
SIG214 on TOP: 11.75,25.95 10.75,26.95 11.75,27.95 12.64,27.95 15.45,30.76 15.45,35.65 15.53,36.03 15.74,36.36 17.34,37.96 17.67,38.17 18.05,38.25 22.73,38.25 22.98,38.32 23.08,38.4 25.04,40.36 25.17,40.58 25.19,40.71 25.19,42.94 25.19,42.98 25.21,43.01 26.09,43.55 26.98,43.01 27,42.98 27,42.94 27,39.6 27,39.57 26.98,39.54 26.9,39.41 26.8,39.29 23.91,36.4 23.81,36.32 23.56,36.25 18.46,36.25 17.45,35.24 17.45,34.05 17.45,34.04 17.45,30.14 17.43,30.01 17.3,29.79 13.76,26.24 13.43,26.03 13.05,25.95
SIG214 on BOTTOM: 12.4,19.5 12.15,19.57 11.97,19.75 11.9,20 11.9,24.99 11.83,25.24 11.75,25.35 10.9,26.2 10.82,26.31 10.75,26.56 10.75,27.5 10.82,27.75 11,27.93 11.25,28 14.85,28 15.1,27.93 15.28,27.75 15.35,27.5 15.35,20 15.28,19.75 15.1,19.57 14.85,19.5

Small or netless copper shapes (teardrops, artwork), in the pictures only: 1 on BOTTOM
